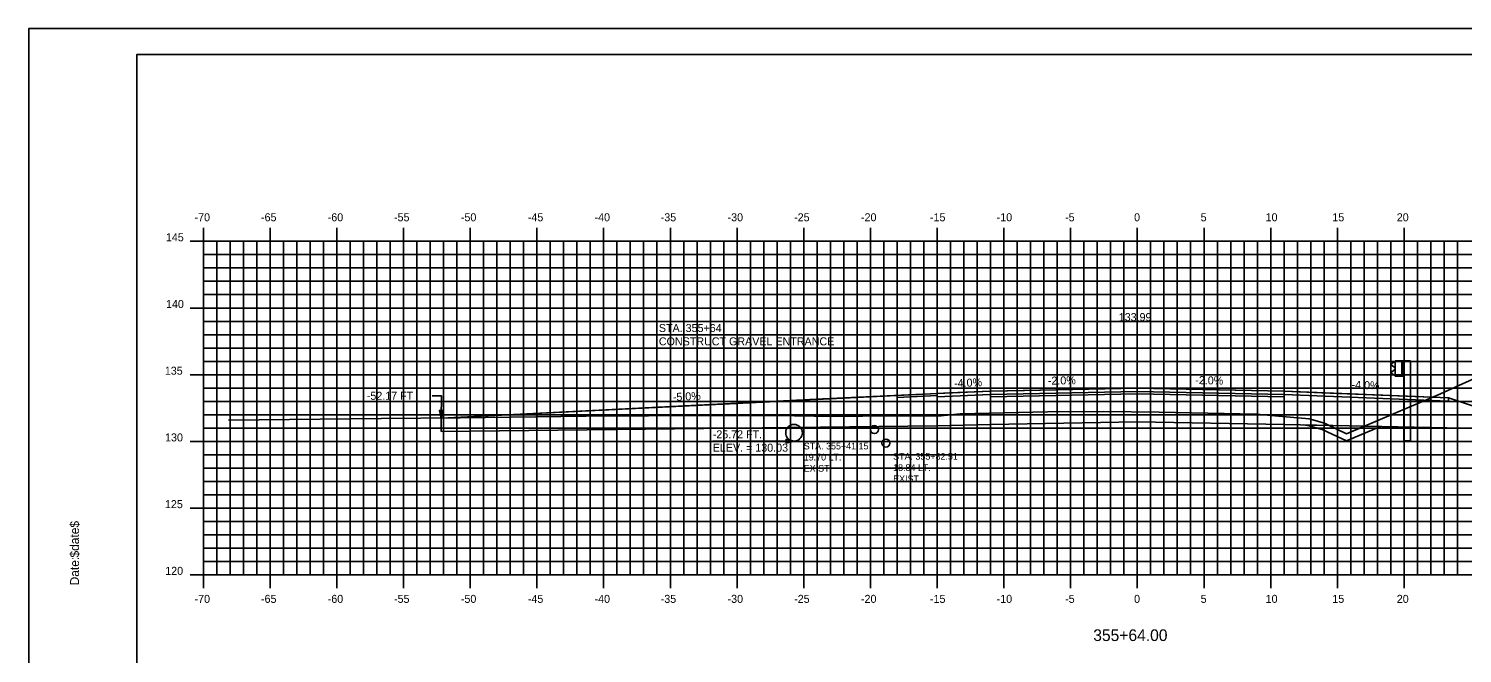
# Model space of a CAD drawing. Extents: x 1145416 to 1145586, y 608981 to 609091.
# Drawn here: x 1145415.8 to 1145523.3, y 609044.5 to 609091.3 of the extents above; entities that cross this region are included whole.
import ezdxf

# ---------------------------------------------------------------- set-up
doc = ezdxf.new("R2010")
doc.units = 0
for name, color, linetype in [('ANNOTATION', 7, 'Continuous'), ('BORDER', 7, 'Continuous'), ('D_Drainage_Culvert', 7, 'Continuous'), ('D_Guardrail_Beam_Rt', 7, 'Continuous'), ('D_Guardrail_ConcBarrier', 7, 'Continuous'), ('D_Roadway_Centerline', 7, 'Continuous'), ('D_Roadway_Centerline_Text', 7, 'Continuous'), ('D_Roadway_Edge_Shoulder', 7, 'Continuous'), ('D_Roadway_Edge_TW', 7, 'Continuous'), ('D_Roadway_Pavement', 7, 'Continuous'), ('D_Roadway_SubGrade', 7, 'Continuous'), ('D_Text_Monospaced', 7, 'Continuous'), ('D_Text_Standard', 7, 'Continuous'), ('H_V ANNOTATION', 7, 'Continuous'), ('MAJOR', 7, 'Continuous'), ('MINOR', 7, 'Continuous'), ('PLOT BOUNDARY', 7, 'Continuous'), ('S_Drainage_Invert', 7, 'Continuous'), ('S_Roadway_Centerline', 7, 'Continuous'), ('SHADING', 7, 'Continuous')]:
    doc.layers.add(name, color=color, linetype=linetype)

msp = doc.modelspace()

# ---------------------------------------------------------------- linework, layer by layer
msp.add_lwpolyline([(1145446.72, 609062.09), (1145475.31, 609063.52), (1145483.89, 609063.94), (1145484.81, 609063.98), (1145487.89, 609064.1), (1145490.43, 609064.16), (1145498.89, 609064.32), (1145501.43, 609064.27), (1145509.89, 609064.1), (1145512.72, 609063.99), (1145522.21, 609063.61), (1145523.87, 609063.06)])
at = {"layer": 'BORDER'}
msp.add_lwpolyline([(1145423.89, 608984.34), (1145583.89, 608984.34), (1145583.89, 609089.34), (1145423.89, 609089.34)], close=True, dxfattribs=at)
at = {"layer": 'D_Drainage_Culvert'}
msp.add_circle((1145473.16, 609060.99), 0.625, dxfattribs=at)
at = {"layer": 'D_Guardrail_Beam_Rt'}
for p, q in [((1145518.12, 609066.28), (1145517.98, 609066.18)), ((1145517.98, 609066.03), (1145518.18, 609065.9)), ((1145518.18, 609065.7), (1145517.98, 609065.56)), ((1145517.98, 609065.42), (1145518.12, 609065.32)), ((1145518.21, 609066.3), (1145518.14, 609066.28)), ((1145518.21, 609065.83), (1145518.21, 609065.76)), ((1145518.14, 609065.31), (1145518.21, 609065.3))]:
    msp.add_line(p, q, dxfattribs=at)
for centre, major_axis, start_param, end_param in [((1145518.03, 609066.11), (-0.0877, 0), 5.323254, 7.243116), ((1145518.03, 609065.49), (-0.0877, 0), 5.323254, 7.243116), ((1145518.15, 609066.24), (-0.0417, 0), 4.907132, 5.323254), ((1145518.13, 609065.83), (0.0789, 0), 0, 0.959931), ((1145518.13, 609065.76), (0.0789, 0), 5.323254, 6.283185), ((1145518.15, 609065.35), (-0.0417, 0), 0.959931, 1.376053)]:
    msp.add_ellipse(centre, major_axis=major_axis, ratio=0.995501, start_param=start_param, end_param=end_param, dxfattribs=at)
at = {"layer": 'D_Guardrail_ConcBarrier'}
for p, q in [((1145518.21, 609066.38), (1145518.9, 609066.38)), ((1145518.21, 609065.22), (1145518.21, 609066.38)), ((1145518.73, 609066.38), (1145518.73, 609065.22)), ((1145518.84, 609066.38), (1145518.84, 609065.22)), ((1145518.9, 609066.38), (1145519.37, 609066.38)), ((1145518.9, 609066.38), (1145518.9, 609065.22)), ((1145519.37, 609066.38), (1145519.37, 609060.38)), ((1145518.9, 609065.22), (1145518.21, 609065.22)), ((1145518.88, 609060.38), (1145518.88, 609065.22)), ((1145518.88, 609060.38), (1145519.37, 609060.38))]:
    msp.add_line(p, q, dxfattribs=at)
at = {"layer": 'D_Roadway_Edge_Shoulder'}
for points in [[(1145483.89, 609063.94), (1145480.89, 609063.79), (1145480.89, 609063.63), (1145483.89, 609063.78)], [(1145487.89, 609064.1), (1145483.89, 609063.94), (1145483.89, 609063.69), (1145487.89, 609063.85)], [(1145509.89, 609064.1), (1145522.21, 609063.61), (1145522.21, 609063.36), (1145509.89, 609063.85)]]:
    msp.add_lwpolyline(points, close=True, dxfattribs=at)
at = {"layer": 'D_Roadway_Edge_TW'}
msp.add_lwpolyline([(1145487.89, 609063.85), (1145487.89, 609064.1), (1145498.89, 609064.32), (1145509.89, 609064.1), (1145509.89, 609063.85), (1145498.89, 609064.07)], close=True, dxfattribs=at)
at = {"layer": 'D_Roadway_Pavement'}
msp.add_lwpolyline([(1145487.89, 609063.69), (1145487.89, 609063.85), (1145498.89, 609064.07), (1145509.89, 609063.85), (1145509.89, 609063.69), (1145498.89, 609063.91)], close=True, dxfattribs=at)
at = {"layer": 'D_Roadway_SubGrade'}
for points in [[(1145446.72, 609061.09), (1145483.89, 609061.52), (1145487.89, 609061.6), (1145487.89, 609063.69), (1145487.89, 609063.85), (1145483.89, 609063.69), (1145483.89, 609063.94), (1145446.72, 609062.09)], [(1145487.89, 609061.6), (1145487.89, 609063.69), (1145498.89, 609063.91), (1145509.89, 609063.69), (1145509.89, 609061.6), (1145498.89, 609061.82)], [(1145509.89, 609063.69), (1145509.89, 609063.85), (1145522.21, 609063.36), (1145522.21, 609063.61), (1145522.21, 609063.61), (1145529.4, 609061.21), (1145509.89, 609061.6)]]:
    msp.add_lwpolyline(points, close=True, dxfattribs=at)
msp.add_lwpolyline([(1145511.33, 609061.58), (1145511.68, 609061.54), (1145512.74, 609061.24), (1145514.57, 609060.38), (1145517.12, 609061.46)], dxfattribs=at)
at = {"layer": 'D_Text_Standard'}
msp.add_line((1145467.07, 609060.37), (1145471.83, 609060.37), dxfattribs=at)
for points in [[(1145446.72, 609062.09), (1145446.73, 609063.76), (1145446.05, 609063.76)], [(1145473.16, 609060.37), (1145472.51, 609060.37), (1145471.83, 609060.37)]]:
    msp.add_lwpolyline(points, dxfattribs=at)
for points in [[(1145446.72, 609062.09), (1145446.58, 609062.67), (1145446.87, 609062.67)], [(1145473.16, 609060.37), (1145472.58, 609060.22), (1145472.58, 609060.52)]]:
    msp.add_lwpolyline(points, close=True, dxfattribs=at)
at = {"layer": 'MAJOR'}
for p, q in [((1145428.89, 609076.34), (1145428.89, 609075.34)), ((1145433.89, 609076.34), (1145433.89, 609075.34)), ((1145438.89, 609076.34), (1145438.89, 609075.34)), ((1145443.89, 609076.34), (1145443.89, 609075.34)), ((1145448.89, 609076.34), (1145448.89, 609075.34)), ((1145453.89, 609076.34), (1145453.89, 609075.34)), ((1145458.89, 609076.34), (1145458.89, 609075.34)), ((1145463.89, 609076.34), (1145463.89, 609075.34)), ((1145468.89, 609076.34), (1145468.89, 609075.34)), ((1145473.89, 609076.34), (1145473.89, 609075.34)), ((1145478.89, 609076.34), (1145478.89, 609075.34)), ((1145483.89, 609076.34), (1145483.89, 609075.34)), ((1145488.89, 609076.34), (1145488.89, 609075.34)), ((1145493.89, 609076.34), (1145493.89, 609075.34)), ((1145498.89, 609076.34), (1145498.89, 609075.34)), ((1145503.89, 609076.34), (1145503.89, 609075.34)), ((1145508.89, 609076.34), (1145508.89, 609075.34)), ((1145513.89, 609076.34), (1145513.89, 609075.34)), ((1145518.89, 609076.34), (1145518.89, 609075.34)), ((1145427.89, 609075.34), (1145428.89, 609075.34)), ((1145428.89, 609075.34), (1145568.89, 609075.34)), ((1145428.89, 609050.34), (1145428.89, 609075.34)), ((1145428.89, 609050.34), (1145428.89, 609075.34)), ((1145428.89, 609075.34), (1145568.89, 609075.34)), ((1145433.89, 609050.34), (1145433.89, 609075.34)), ((1145438.89, 609050.34), (1145438.89, 609075.34)), ((1145443.89, 609050.34), (1145443.89, 609075.34)), ((1145448.89, 609050.34), (1145448.89, 609075.34)), ((1145453.89, 609050.34), (1145453.89, 609075.34)), ((1145458.89, 609050.34), (1145458.89, 609075.34)), ((1145463.89, 609050.34), (1145463.89, 609075.34)), ((1145468.89, 609050.34), (1145468.89, 609075.34)), ((1145473.89, 609050.34), (1145473.89, 609075.34)), ((1145478.89, 609050.34), (1145478.89, 609075.34)), ((1145483.89, 609050.34), (1145483.89, 609075.34)), ((1145488.89, 609050.34), (1145488.89, 609075.34)), ((1145493.89, 609050.34), (1145493.89, 609075.34)), ((1145498.89, 609050.34), (1145498.89, 609075.34)), ((1145503.89, 609050.34), (1145503.89, 609075.34)), ((1145508.89, 609050.34), (1145508.89, 609075.34)), ((1145513.89, 609050.34), (1145513.89, 609075.34)), ((1145518.89, 609050.34), (1145518.89, 609075.34)), ((1145427.89, 609070.34), (1145428.89, 609070.34)), ((1145428.89, 609070.34), (1145568.89, 609070.34)), ((1145427.89, 609065.34), (1145428.89, 609065.34)), ((1145428.89, 609065.34), (1145568.89, 609065.34)), ((1145427.89, 609060.34), (1145428.89, 609060.34)), ((1145428.89, 609060.34), (1145568.89, 609060.34)), ((1145427.89, 609055.34), (1145428.89, 609055.34)), ((1145428.89, 609055.34), (1145568.89, 609055.34)), ((1145427.89, 609050.34), (1145428.89, 609050.34)), ((1145428.89, 609050.34), (1145568.89, 609050.34)), ((1145428.89, 609050.34), (1145568.89, 609050.34)), ((1145428.89, 609049.33), (1145428.89, 609050.34)), ((1145433.89, 609049.33), (1145433.89, 609050.34)), ((1145438.89, 609049.33), (1145438.89, 609050.34)), ((1145443.89, 609049.33), (1145443.89, 609050.34)), ((1145448.89, 609049.33), (1145448.89, 609050.34)), ((1145453.89, 609049.33), (1145453.89, 609050.34)), ((1145458.89, 609049.33), (1145458.89, 609050.34)), ((1145463.89, 609049.33), (1145463.89, 609050.34)), ((1145468.89, 609049.33), (1145468.89, 609050.34)), ((1145473.89, 609049.33), (1145473.89, 609050.34)), ((1145478.89, 609049.33), (1145478.89, 609050.34)), ((1145483.89, 609049.33), (1145483.89, 609050.34)), ((1145488.89, 609049.33), (1145488.89, 609050.34)), ((1145493.89, 609049.33), (1145493.89, 609050.34)), ((1145498.89, 609049.33), (1145498.89, 609050.34)), ((1145503.89, 609049.33), (1145503.89, 609050.34)), ((1145508.89, 609049.33), (1145508.89, 609050.34)), ((1145513.89, 609049.33), (1145513.89, 609050.34)), ((1145518.89, 609049.33), (1145518.89, 609050.34))]:
    msp.add_line(p, q, dxfattribs=at)
at = {"layer": 'MINOR'}
for p, q in [((1145428.89, 609050.34), (1145428.89, 609075.34)), ((1145429.89, 609050.34), (1145429.89, 609075.34)), ((1145430.89, 609050.34), (1145430.89, 609075.34)), ((1145431.89, 609050.34), (1145431.89, 609075.34)), ((1145432.89, 609050.34), (1145432.89, 609075.34)), ((1145434.89, 609050.34), (1145434.89, 609075.34)), ((1145435.89, 609050.34), (1145435.89, 609075.34)), ((1145436.89, 609050.34), (1145436.89, 609075.34)), ((1145437.89, 609050.34), (1145437.89, 609075.34)), ((1145439.89, 609050.34), (1145439.89, 609075.34)), ((1145440.89, 609050.34), (1145440.89, 609075.34)), ((1145441.89, 609050.34), (1145441.89, 609075.34)), ((1145442.89, 609050.34), (1145442.89, 609075.34)), ((1145444.89, 609050.34), (1145444.89, 609075.34)), ((1145445.89, 609050.34), (1145445.89, 609075.34)), ((1145446.89, 609050.34), (1145446.89, 609075.34)), ((1145447.89, 609050.34), (1145447.89, 609075.34)), ((1145449.89, 609050.34), (1145449.89, 609075.34)), ((1145450.89, 609050.34), (1145450.89, 609075.34)), ((1145451.89, 609050.34), (1145451.89, 609075.34)), ((1145452.89, 609050.34), (1145452.89, 609075.34)), ((1145454.89, 609050.34), (1145454.89, 609075.34)), ((1145455.89, 609050.34), (1145455.89, 609075.34)), ((1145456.89, 609050.34), (1145456.89, 609075.34)), ((1145457.89, 609050.34), (1145457.89, 609075.34)), ((1145459.89, 609050.34), (1145459.89, 609075.34)), ((1145460.89, 609050.34), (1145460.89, 609075.34)), ((1145461.89, 609050.34), (1145461.89, 609075.34)), ((1145462.89, 609050.34), (1145462.89, 609075.34)), ((1145464.89, 609050.34), (1145464.89, 609075.34)), ((1145465.89, 609050.34), (1145465.89, 609075.34)), ((1145466.89, 609050.34), (1145466.89, 609075.34)), ((1145467.89, 609050.34), (1145467.89, 609075.34)), ((1145469.89, 609050.34), (1145469.89, 609075.34)), ((1145470.89, 609050.34), (1145470.89, 609075.34)), ((1145471.89, 609050.34), (1145471.89, 609075.34)), ((1145472.89, 609050.34), (1145472.89, 609075.34)), ((1145474.89, 609050.34), (1145474.89, 609075.34)), ((1145475.89, 609050.34), (1145475.89, 609075.34)), ((1145476.89, 609050.34), (1145476.89, 609075.34)), ((1145477.89, 609050.34), (1145477.89, 609075.34)), ((1145479.89, 609050.34), (1145479.89, 609075.34)), ((1145480.89, 609050.34), (1145480.89, 609075.34)), ((1145481.89, 609050.34), (1145481.89, 609075.34)), ((1145482.89, 609050.34), (1145482.89, 609075.34)), ((1145484.89, 609050.34), (1145484.89, 609075.34)), ((1145485.89, 609050.34), (1145485.89, 609075.34)), ((1145486.89, 609050.34), (1145486.89, 609075.34)), ((1145487.89, 609050.34), (1145487.89, 609075.34)), ((1145489.89, 609050.34), (1145489.89, 609075.34)), ((1145490.89, 609050.34), (1145490.89, 609075.34)), ((1145491.89, 609050.34), (1145491.89, 609075.34)), ((1145492.89, 609050.34), (1145492.89, 609075.34)), ((1145494.89, 609050.34), (1145494.89, 609075.34)), ((1145495.89, 609050.34), (1145495.89, 609075.34)), ((1145496.89, 609050.34), (1145496.89, 609075.34)), ((1145497.89, 609050.34), (1145497.89, 609075.34)), ((1145499.89, 609050.34), (1145499.89, 609075.34)), ((1145500.89, 609050.34), (1145500.89, 609075.34)), ((1145501.89, 609050.34), (1145501.89, 609075.34)), ((1145502.89, 609050.34), (1145502.89, 609075.34)), ((1145504.89, 609050.34), (1145504.89, 609075.34)), ((1145505.89, 609050.34), (1145505.89, 609075.34)), ((1145506.89, 609050.34), (1145506.89, 609075.34)), ((1145507.89, 609050.34), (1145507.89, 609075.34)), ((1145509.89, 609050.34), (1145509.89, 609075.34)), ((1145510.89, 609050.34), (1145510.89, 609075.34)), ((1145511.89, 609050.34), (1145511.89, 609075.34)), ((1145512.89, 609050.34), (1145512.89, 609075.34)), ((1145514.89, 609050.34), (1145514.89, 609075.34)), ((1145515.89, 609050.34), (1145515.89, 609075.34)), ((1145516.89, 609050.34), (1145516.89, 609075.34)), ((1145517.89, 609050.34), (1145517.89, 609075.34)), ((1145519.89, 609050.34), (1145519.89, 609075.34)), ((1145520.89, 609050.34), (1145520.89, 609075.34)), ((1145521.89, 609050.34), (1145521.89, 609075.34)), ((1145522.89, 609050.34), (1145522.89, 609075.34)), ((1145428.89, 609074.34), (1145568.89, 609074.34)), ((1145428.89, 609074.34), (1145429.89, 609074.34)), ((1145428.89, 609073.34), (1145568.89, 609073.34)), ((1145428.89, 609073.34), (1145429.89, 609073.34)), ((1145428.89, 609072.34), (1145568.89, 609072.34)), ((1145428.89, 609072.34), (1145429.89, 609072.34)), ((1145428.89, 609071.34), (1145568.89, 609071.34)), ((1145428.89, 609071.34), (1145429.89, 609071.34)), ((1145428.89, 609069.34), (1145568.89, 609069.34)), ((1145428.89, 609069.34), (1145429.89, 609069.34)), ((1145428.89, 609068.34), (1145568.89, 609068.34)), ((1145428.89, 609068.34), (1145429.89, 609068.34)), ((1145428.89, 609067.34), (1145568.89, 609067.34)), ((1145428.89, 609067.34), (1145429.89, 609067.34)), ((1145428.89, 609066.34), (1145568.89, 609066.34)), ((1145428.89, 609066.34), (1145429.89, 609066.34)), ((1145428.89, 609064.34), (1145568.89, 609064.34)), ((1145428.89, 609064.34), (1145429.89, 609064.34)), ((1145428.89, 609063.34), (1145568.89, 609063.34)), ((1145428.89, 609063.34), (1145429.89, 609063.34)), ((1145428.89, 609062.34), (1145568.89, 609062.34)), ((1145428.89, 609062.34), (1145429.89, 609062.34)), ((1145428.89, 609061.34), (1145568.89, 609061.34)), ((1145428.89, 609061.34), (1145429.89, 609061.34)), ((1145428.89, 609059.34), (1145568.89, 609059.34)), ((1145428.89, 609059.34), (1145429.89, 609059.34)), ((1145428.89, 609058.34), (1145568.89, 609058.34)), ((1145428.89, 609058.34), (1145429.89, 609058.34)), ((1145428.89, 609057.34), (1145568.89, 609057.34)), ((1145428.89, 609057.34), (1145429.89, 609057.34)), ((1145428.89, 609056.34), (1145568.89, 609056.34)), ((1145428.89, 609056.34), (1145429.89, 609056.34)), ((1145428.89, 609054.34), (1145568.89, 609054.34)), ((1145428.89, 609054.34), (1145429.89, 609054.34)), ((1145428.89, 609053.34), (1145568.89, 609053.34)), ((1145428.89, 609053.34), (1145429.89, 609053.34)), ((1145428.89, 609052.34), (1145568.89, 609052.34)), ((1145428.89, 609052.34), (1145429.89, 609052.34)), ((1145428.89, 609051.34), (1145568.89, 609051.34)), ((1145428.89, 609051.34), (1145429.89, 609051.34))]:
    msp.add_line(p, q, dxfattribs=at)
at = {"layer": 'PLOT BOUNDARY'}
msp.add_lwpolyline([(1145415.8, 608981.28), (1145585.8, 608981.28), (1145585.8, 609091.28), (1145415.8, 609091.28)], close=True, dxfattribs=at)
at = {"layer": 'S_Drainage_Invert'}
for centre in [(1145479.19, 609061.23), (1145480.05, 609060.21)]:
    msp.add_circle(centre, 0.3, dxfattribs=at)
at = {"layer": 'S_Roadway_Centerline'}
msp.add_lwpolyline([(1145430.77, 609061.93), (1145442.22, 609062.06), (1145448.13, 609062.1), (1145457.59, 609062.23), (1145466.92, 609062.29), (1145471.75, 609062.28), (1145476.11, 609062.2), (1145480.46, 609062.26), (1145483.94, 609062.24), (1145485.61, 609062.41), (1145492.15, 609062.55), (1145496.36, 609062.59), (1145500.54, 609062.54), (1145507.82, 609062.39), (1145509.19, 609062.27), (1145511.77, 609062.04), (1145512.92, 609061.71), (1145514.58, 609060.92), (1145521.61, 609063.91), (1145525.15, 609065.5), (1145538.55, 609065.91), (1145549.34, 609066.09)], dxfattribs=at)
at = {"layer": 'SHADING'}
for p, q in [((1145513.28, 609061.54), (1145511.68, 609061.57)), ((1145517.12, 609061.46), (1145515.9, 609061.48))]:
    msp.add_line(p, q, dxfattribs=at)
for points in [[(1145511.68, 609061.57), (1145511.68, 609061.54)], [(1145511.68, 609061.54), (1145512.74, 609061.24), (1145514.57, 609060.38), (1145517.12, 609061.46)], [(1145515.9, 609061.48), (1145514.58, 609060.92), (1145513.28, 609061.54)]]:
    msp.add_lwpolyline(points, dxfattribs=at)

# ---------------------------------------------------------------- texts
at = {"layer": 'ANNOTATION'}
for s, p in [('STA. 355+64', (1145463.03, 609068.54)), ('CONSTRUCT GRAVEL ENTRANCE', (1145463.03, 609067.54))]:
    msp.add_text(s, height=0.6, dxfattribs=at).set_placement(p)
for s, rotation, p in [('-4.0%', 2.2906, (1145485.17, 609064.4)), ('-2.0%', 1.1458, (1145492.19, 609064.59)), ('-2.0%', 358.8542, (1145503.23, 609064.64)), ('-4.0%', 357.7094, (1145514.94, 609064.3)), ('-5.0%', 2.8624, (1145464.09, 609063.36))]:
    msp.add_text(s, height=0.6, rotation=rotation, dxfattribs=at).set_placement(p)
at = {"layer": 'BORDER'}
for s, p in [('$date$', (1145419.57, 609051.64)), ('Date:', (1145419.57, 609049.55))]:
    msp.add_text(s, height=0.67, rotation=90, dxfattribs=at).set_placement(p)
at = {"layer": 'D_Roadway_Centerline'}
for s, p in [('C', (1145498.88, 609064.32)), ('L', (1145498.89, 609064.32))]:
    msp.add_text(s, height=0.0146, dxfattribs=at).set_placement(p)
at = {"layer": 'D_Roadway_Centerline_Text'}
msp.add_text('133.99', height=0.6, dxfattribs=at).set_placement((1145497.5, 609069.36))
at = {"layer": 'D_Text_Monospaced'}
for s, p in [('STA. 355+41.15', (1145473.89, 609059.74)), ('19.70 LT.', (1145473.89, 609058.91)), ('STA. 355+82.51', (1145480.59, 609058.97)), ('EXIST. ', (1145473.89, 609058.07)), ('18.84 LT.', (1145480.59, 609058.13)), ('EXIST. ', (1145480.59, 609057.29))]:
    msp.add_text(s, height=0.5, dxfattribs=at).set_placement(p)
at = {"layer": 'D_Text_Standard'}
for s, p in [('-52.17 FT', (1145441.14, 609063.46)), ('-25.72 FT.', (1145467.07, 609060.57)), ('ELEV. = 130.03', (1145467.07, 609059.57))]:
    msp.add_text(s, height=0.6, dxfattribs=at).set_placement(p)
at = {"layer": 'H_V ANNOTATION'}
for s, height, p in [('-70', 0.6, (1145428.23, 609076.84)), ('-65', 0.6, (1145433.21, 609076.84)), ('-60', 0.6, (1145438.21, 609076.84)), ('-55', 0.6, (1145443.18, 609076.84)), ('-50', 0.6, (1145448.19, 609076.84)), ('-45', 0.6, (1145453.21, 609076.84)), ('-40', 0.6, (1145458.21, 609076.84)), ('-35', 0.6, (1145463.17, 609076.84)), ('-30', 0.6, (1145468.18, 609076.84)), ('-25', 0.6, (1145473.17, 609076.84)), ('-20', 0.6, (1145478.18, 609076.84)), ('-15', 0.6, (1145483.35, 609076.84)), ('-10', 0.6, (1145488.35, 609076.84)), ('-5', 0.6, (1145493.48, 609076.84)), ('0', 0.6, (1145498.65, 609076.84)), ('5', 0.6, (1145503.64, 609076.84)), ('10', 0.6, (1145508.51, 609076.84)), ('15', 0.6, (1145513.51, 609076.84)), ('20', 0.6, (1145518.34, 609076.84)), ('145', 0.6, (1145426.08, 609075.34)), ('140', 0.6, (1145426.09, 609070.34)), ('135', 0.6, (1145426, 609065.34)), ('130', 0.6, (1145426.02, 609060.34)), ('125', 0.6, (1145426.01, 609055.34)), ('120', 0.6, (1145426.03, 609050.34)), ('-70', 0.6, (1145428.23, 609048.24)), ('-65', 0.6, (1145433.21, 609048.24)), ('-60', 0.6, (1145438.21, 609048.24)), ('-55', 0.6, (1145443.18, 609048.24)), ('-50', 0.6, (1145448.19, 609048.24)), ('-45', 0.6, (1145453.21, 609048.24)), ('-40', 0.6, (1145458.21, 609048.24)), ('-35', 0.6, (1145463.17, 609048.24)), ('-30', 0.6, (1145468.18, 609048.24)), ('-25', 0.6, (1145473.17, 609048.24)), ('-20', 0.6, (1145478.18, 609048.24)), ('-15', 0.6, (1145483.35, 609048.24)), ('-10', 0.6, (1145488.35, 609048.24)), ('-5', 0.6, (1145493.48, 609048.24)), ('0', 0.6, (1145498.65, 609048.24)), ('5', 0.6, (1145503.64, 609048.24)), ('10', 0.6, (1145508.51, 609048.24)), ('15', 0.6, (1145513.51, 609048.24)), ('20', 0.6, (1145518.34, 609048.24)), ('355+64.00', 0.875, (1145495.59, 609045.38))]:
    msp.add_text(s, height=height, dxfattribs=at).set_placement(p)
at = {"layer": 'MAJOR'}
msp.add_text('-', height=0.006, dxfattribs=at).set_placement((1145428.88, 609050.34))
at = {"layer": 'S_Roadway_Centerline'}
for s in ['C', 'L']:
    msp.add_text(s, height=0.0146, dxfattribs=at).set_placement((1145496.35, 609062.59))

doc.saveas('drawing.dxf')
